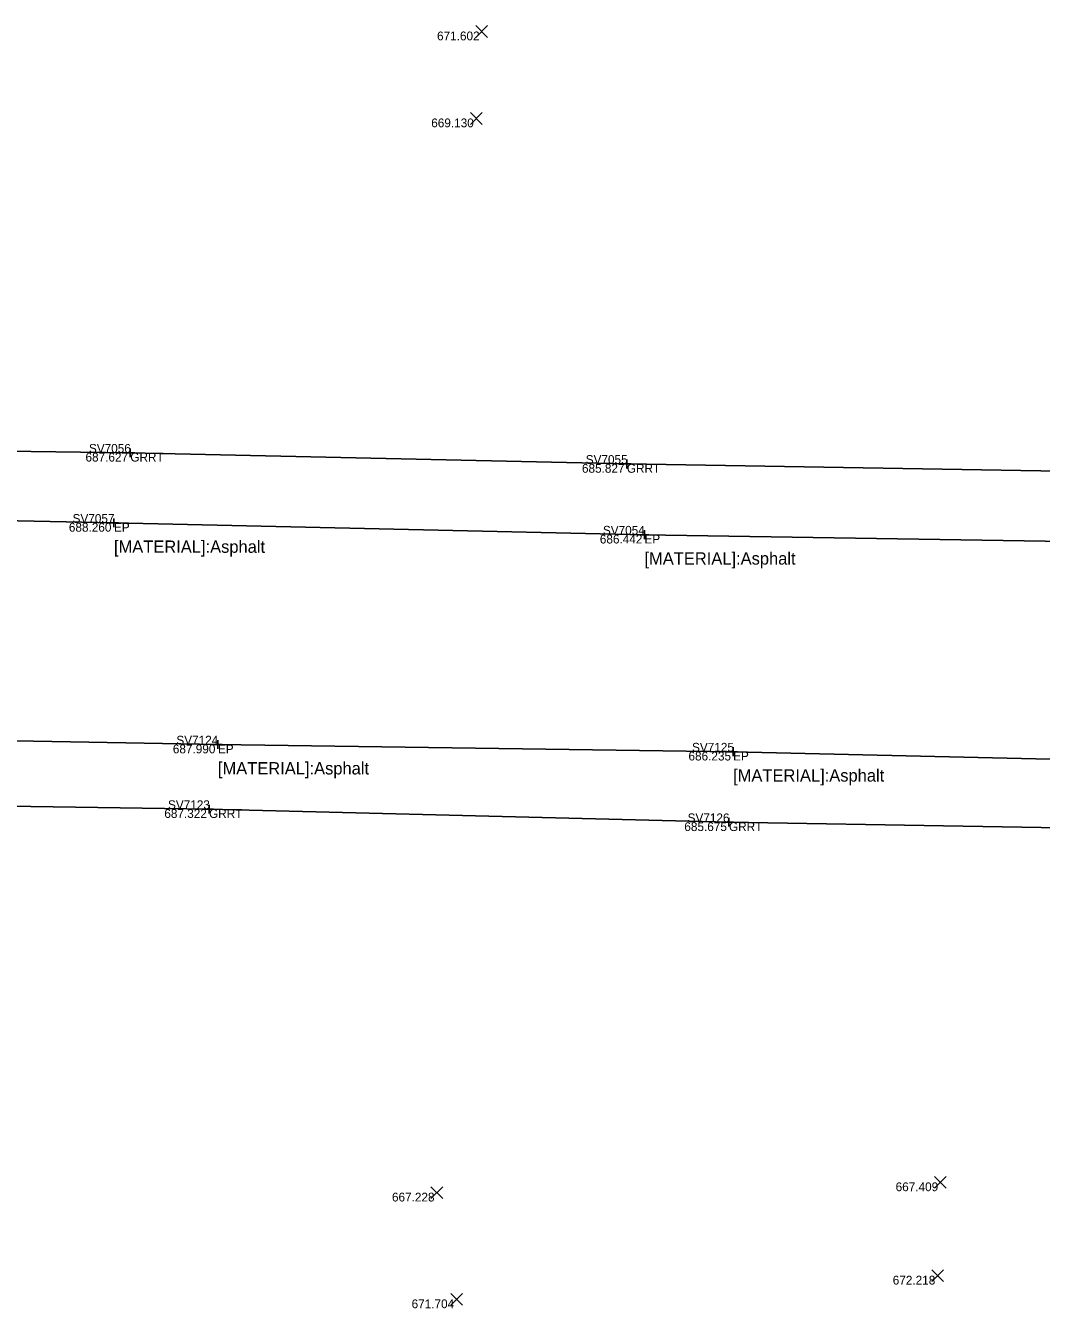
# Model space of a CAD drawing. Extents: x 1660019 to 1662995, y 619975 to 620342.
# Drawn here: x 1661875.4 to 1661990.8, y 620144.2 to 620290 of the extents above; entities that cross this region are included whole.
import ezdxf

# ---------------------------------------------------------------- set-up
doc = ezdxf.new("R2010")
doc.units = 0
for name, color, linetype in [('BR_X_Rail_Object', 7, 'Continuous'), ('PV_X_EOP', 7, 'Continuous'), ('RD_P_GR_Lt', 7, 'Continuous'), ('RD_P_GR_Rt', 7, 'Continuous'), ('RD_X_GR_Bar', 7, 'Continuous'), ('RD_X_GR_Rt', 7, 'Continuous'), ('RD_X_Wall', 7, 'Continuous'), ('SV_X_Text', 7, 'Continuous')]:
    doc.layers.add(name, color=color, linetype=linetype)

msp = doc.modelspace()

# ---------------------------------------------------------------- linework, layer by layer
at = {"layer": 'PV_X_EOP'}
for points in [[(1662111.67, 620229.32), (1662054.93, 620230.37), (1661998.42, 620231.32), (1661945.73, 620232.16), (1661885.47, 620233.5), (1661831.11, 620234.65), (1661773.24, 620235.9), (1661719.2, 620236.82), (1661662.34, 620238.11), (1661602.46, 620239.35), (1661551.29, 620241.52)], [(1661543.6, 620215.08), (1661595.45, 620214.35), (1661653.94, 620213.41), (1661707.72, 620212.24), (1661760.97, 620211.02), (1661840.69, 620209.32), (1661897.28, 620208.31), (1661955.8, 620207.5), (1662009.84, 620206.22), (1662063.33, 620205.17), (1662115.71, 620204.21)]]:
    msp.add_lwpolyline(points, dxfattribs=at)
at = {"layer": 'RD_P_GR_Lt'}
for p, q in [((1661886.83, 620241.47), (1661887.83, 620241.47)), ((1661887.33, 620241.97), (1661887.33, 620240.97)), ((1661887.33, 620241.47), (1661887.33, 620241.47)), ((1661943.23, 620240.2), (1661944.23, 620240.2)), ((1661943.73, 620240.7), (1661943.73, 620239.7)), ((1661943.73, 620240.2), (1661943.73, 620240.2)), ((1661884.97, 620233.5), (1661885.97, 620233.5)), ((1661885.47, 620234), (1661885.47, 620233)), ((1661885.47, 620233.5), (1661885.47, 620233.5)), ((1661945.23, 620232.16), (1661946.23, 620232.16)), ((1661945.73, 620232.66), (1661945.73, 620231.66)), ((1661945.73, 620232.16), (1661945.73, 620232.16)), ((1661897.28, 620208.81), (1661897.28, 620207.81)), ((1661896.78, 620208.31), (1661897.78, 620208.31)), ((1661897.28, 620208.31), (1661897.28, 620208.31)), ((1661955.3, 620207.5), (1661956.3, 620207.5)), ((1661955.8, 620208), (1661955.8, 620207)), ((1661955.8, 620207.5), (1661955.8, 620207.5)), ((1661896.27, 620201.47), (1661896.27, 620200.47)), ((1661895.77, 620200.97), (1661896.77, 620200.97)), ((1661896.27, 620200.97), (1661896.27, 620200.97)), ((1661955.33, 620199.98), (1661955.33, 620198.98)), ((1661954.83, 620199.48), (1661955.83, 620199.48)), ((1661955.33, 620199.48), (1661955.33, 620199.48))]:
    msp.add_line(p, q, dxfattribs=at)
at = {"layer": 'RD_P_GR_Rt'}
for p, q in [((1661926.57, 620288.68), (1661927.91, 620290.01)), ((1661926.57, 620290.01), (1661927.91, 620288.68)), ((1661925.96, 620278.79), (1661927.29, 620280.13)), ((1661925.96, 620280.13), (1661927.29, 620278.79)), ((1661978.68, 620157.88), (1661980.01, 620159.21)), ((1661978.68, 620159.21), (1661980.01, 620157.88)), ((1661921.48, 620156.71), (1661922.82, 620158.05)), ((1661921.48, 620158.05), (1661922.82, 620156.71)), ((1661978.36, 620147.27), (1661979.69, 620148.61)), ((1661978.36, 620148.61), (1661979.69, 620147.27)), ((1661923.74, 620144.58), (1661925.07, 620145.92)), ((1661923.74, 620145.92), (1661925.07, 620144.58))]:
    msp.add_line(p, q, dxfattribs=at)
at = {"layer": 'RD_X_GR_Rt'}
for points in [[(1662112.15, 620237.06), (1662055.66, 620238.25), (1661999.68, 620239.27), (1661943.73, 620240.2), (1661887.33, 620241.47), (1661831.01, 620242.22), (1661774.89, 620243.8), (1661718.6, 620244.37), (1661662.44, 620245.38), (1661601.89, 620244.64), (1661537.84, 620244.62)], [(1661527.71, 620211.76), (1661596.63, 620209.07), (1661652.77, 620205.71), (1661709.09, 620204.45), (1661758.9, 620203.47), (1661840.54, 620201.81), (1661896.27, 620200.97), (1661955.33, 620199.48), (1662008.56, 620198.59), (1662063.03, 620197.38), (1662114.92, 620196.42)]]:
    msp.add_lwpolyline(points, dxfattribs=at)

# ---------------------------------------------------------------- texts
at = {"layer": 'BR_X_Rail_Object'}
for s, p in [('GRRT', (1661887.33, 620240.47)), ('GRRT', (1661943.73, 620239.2)), ('EP', (1661885.47, 620232.5)), ('EP', (1661945.73, 620231.16)), ('EP', (1661897.28, 620207.31)), ('EP', (1661955.8, 620206.5)), ('GRRT', (1661896.27, 620199.97)), ('GRRT', (1661955.33, 620198.48))]:
    msp.add_text(s, height=1, dxfattribs=at).set_placement(p)
at = {"layer": 'RD_X_GR_Bar'}
for s, p in [('671.602', (1661922.17, 620288.34)), ('669.130', (1661921.51, 620278.46)), ('687.627', (1661882.24, 620240.47)), ('685.827', (1661938.63, 620239.2)), ('688.260', (1661880.35, 620232.5)), ('686.442', (1661940.66, 620231.16)), ('687.990', (1661892.16, 620207.31)), ('686.235', (1661950.73, 620206.5)), ('687.322', (1661891.19, 620199.97)), ('685.675', (1661950.26, 620198.48)), ('667.409', (1661974.26, 620157.55)), ('667.228', (1661917.05, 620156.38)), ('672.218', (1661973.93, 620146.94)), ('671.704', (1661919.28, 620144.25))]:
    msp.add_text(s, height=1, dxfattribs=at).set_placement(p)
at = {"layer": 'RD_X_Wall'}
for s, p in [('SV7056', (1661882.63, 620241.47)), ('SV7055', (1661939.06, 620240.2)), ('SV7057', (1661880.77, 620233.5)), ('SV7054', (1661941.01, 620232.16)), ('SV7124', (1661892.56, 620208.31)), ('SV7125', (1661951.13, 620207.5)), ('SV7123', (1661891.61, 620200.97)), ('SV7126', (1661950.63, 620199.48))]:
    msp.add_text(s, height=1, dxfattribs=at).set_placement(p)
at = {"layer": 'SV_X_Text'}
for p in [(1661885.47, 620230.1), (1661945.73, 620228.76), (1661897.28, 620204.91), (1661955.8, 620204.1)]:
    msp.add_text('[MATERIAL]:Asphalt', height=1.4, dxfattribs=at).set_placement(p)

doc.saveas('drawing.dxf')
